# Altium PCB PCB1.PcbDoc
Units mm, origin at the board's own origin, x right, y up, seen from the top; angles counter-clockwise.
Board outline 70 x 70 mm, 2 copper layers (Top Layer, Bottom Layer); 5 components, 87 nets, 200 pads, 0 vias.
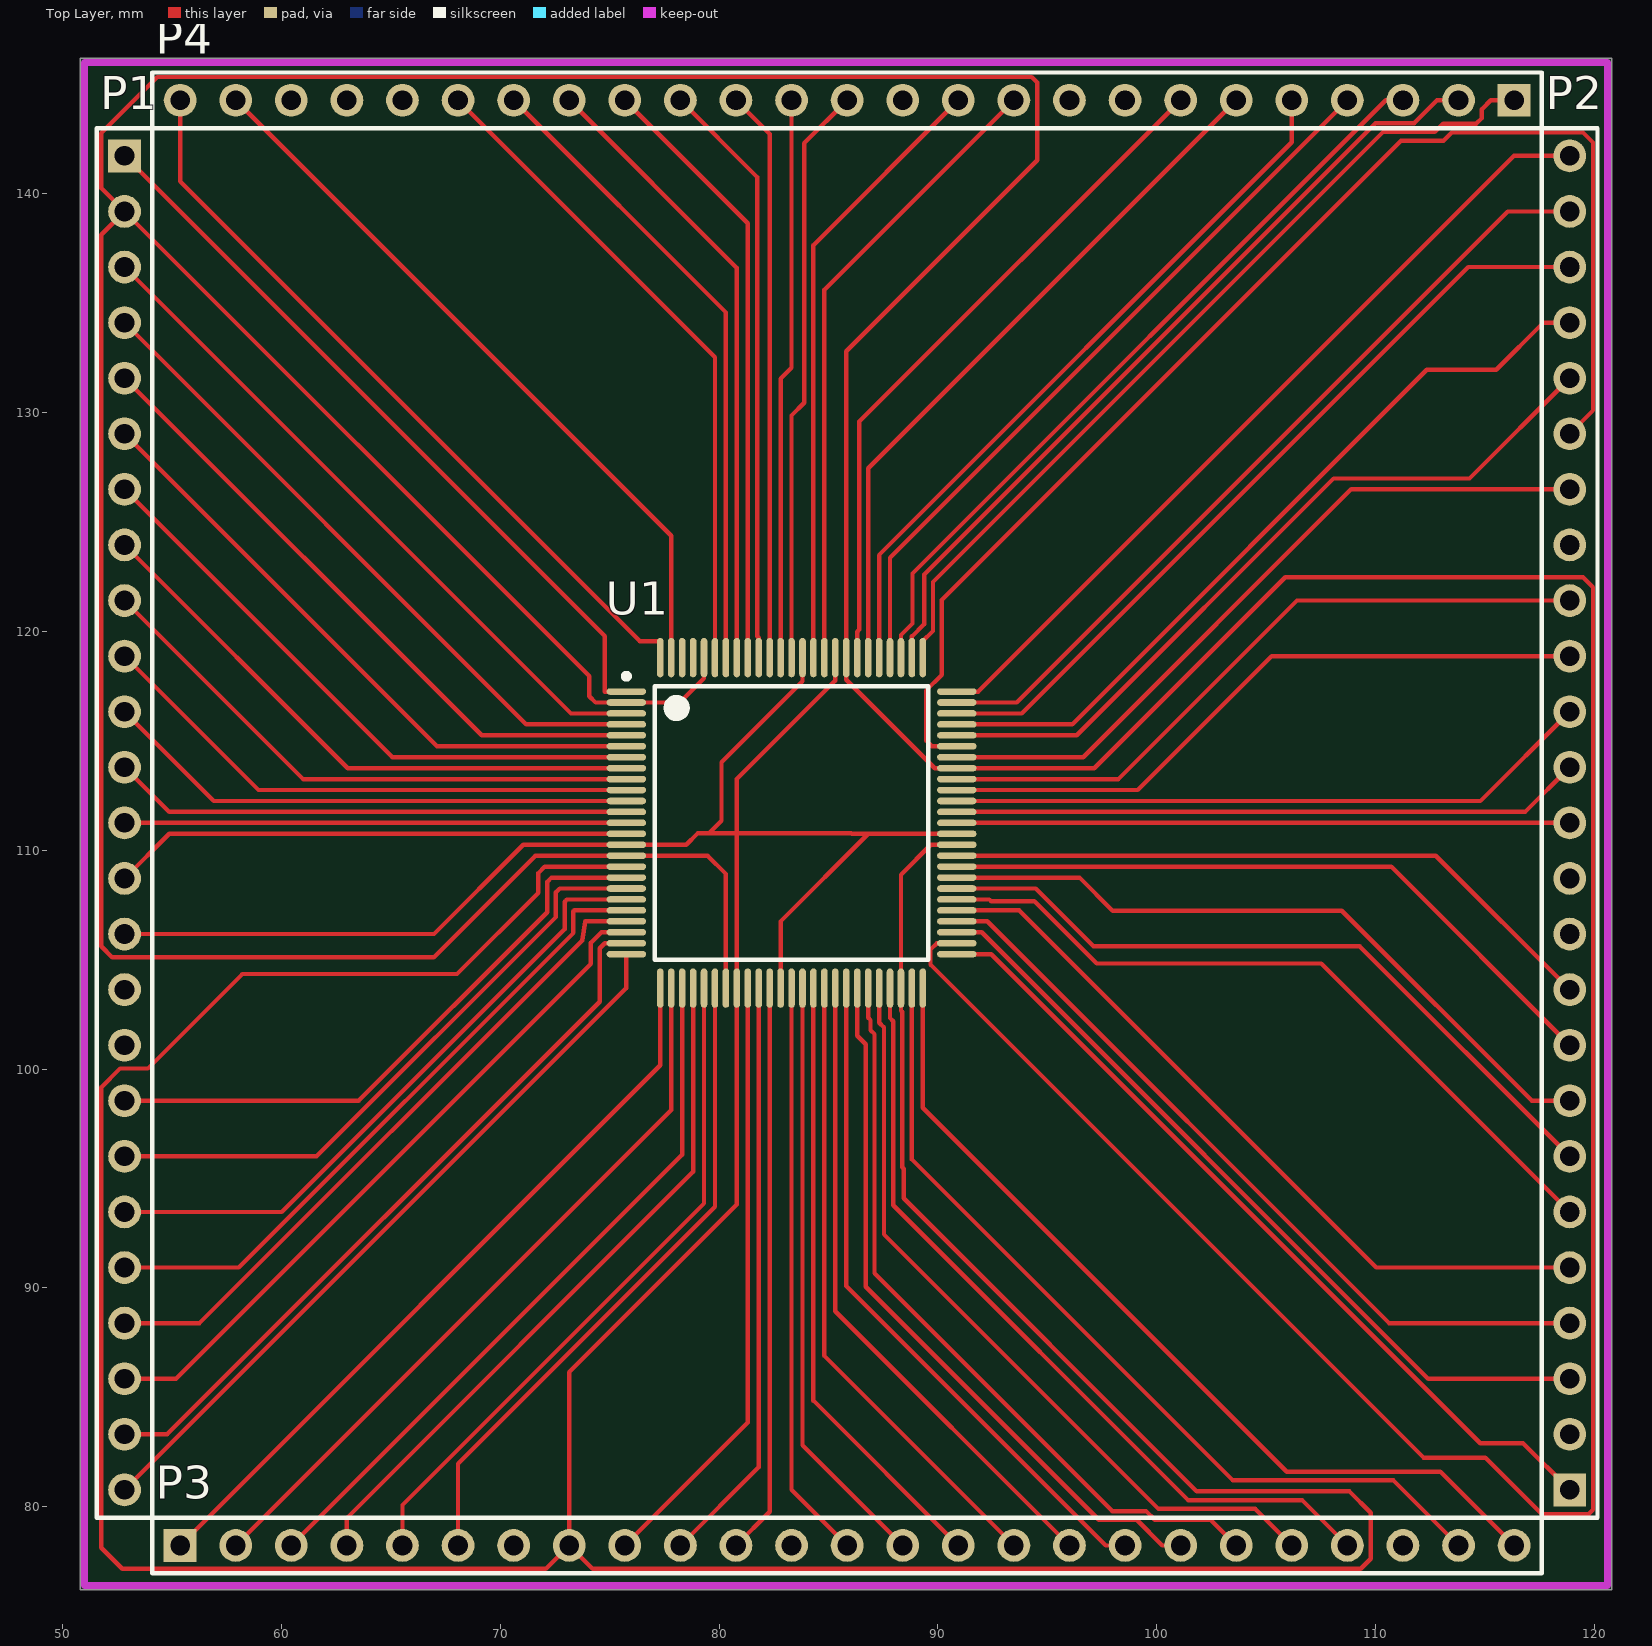
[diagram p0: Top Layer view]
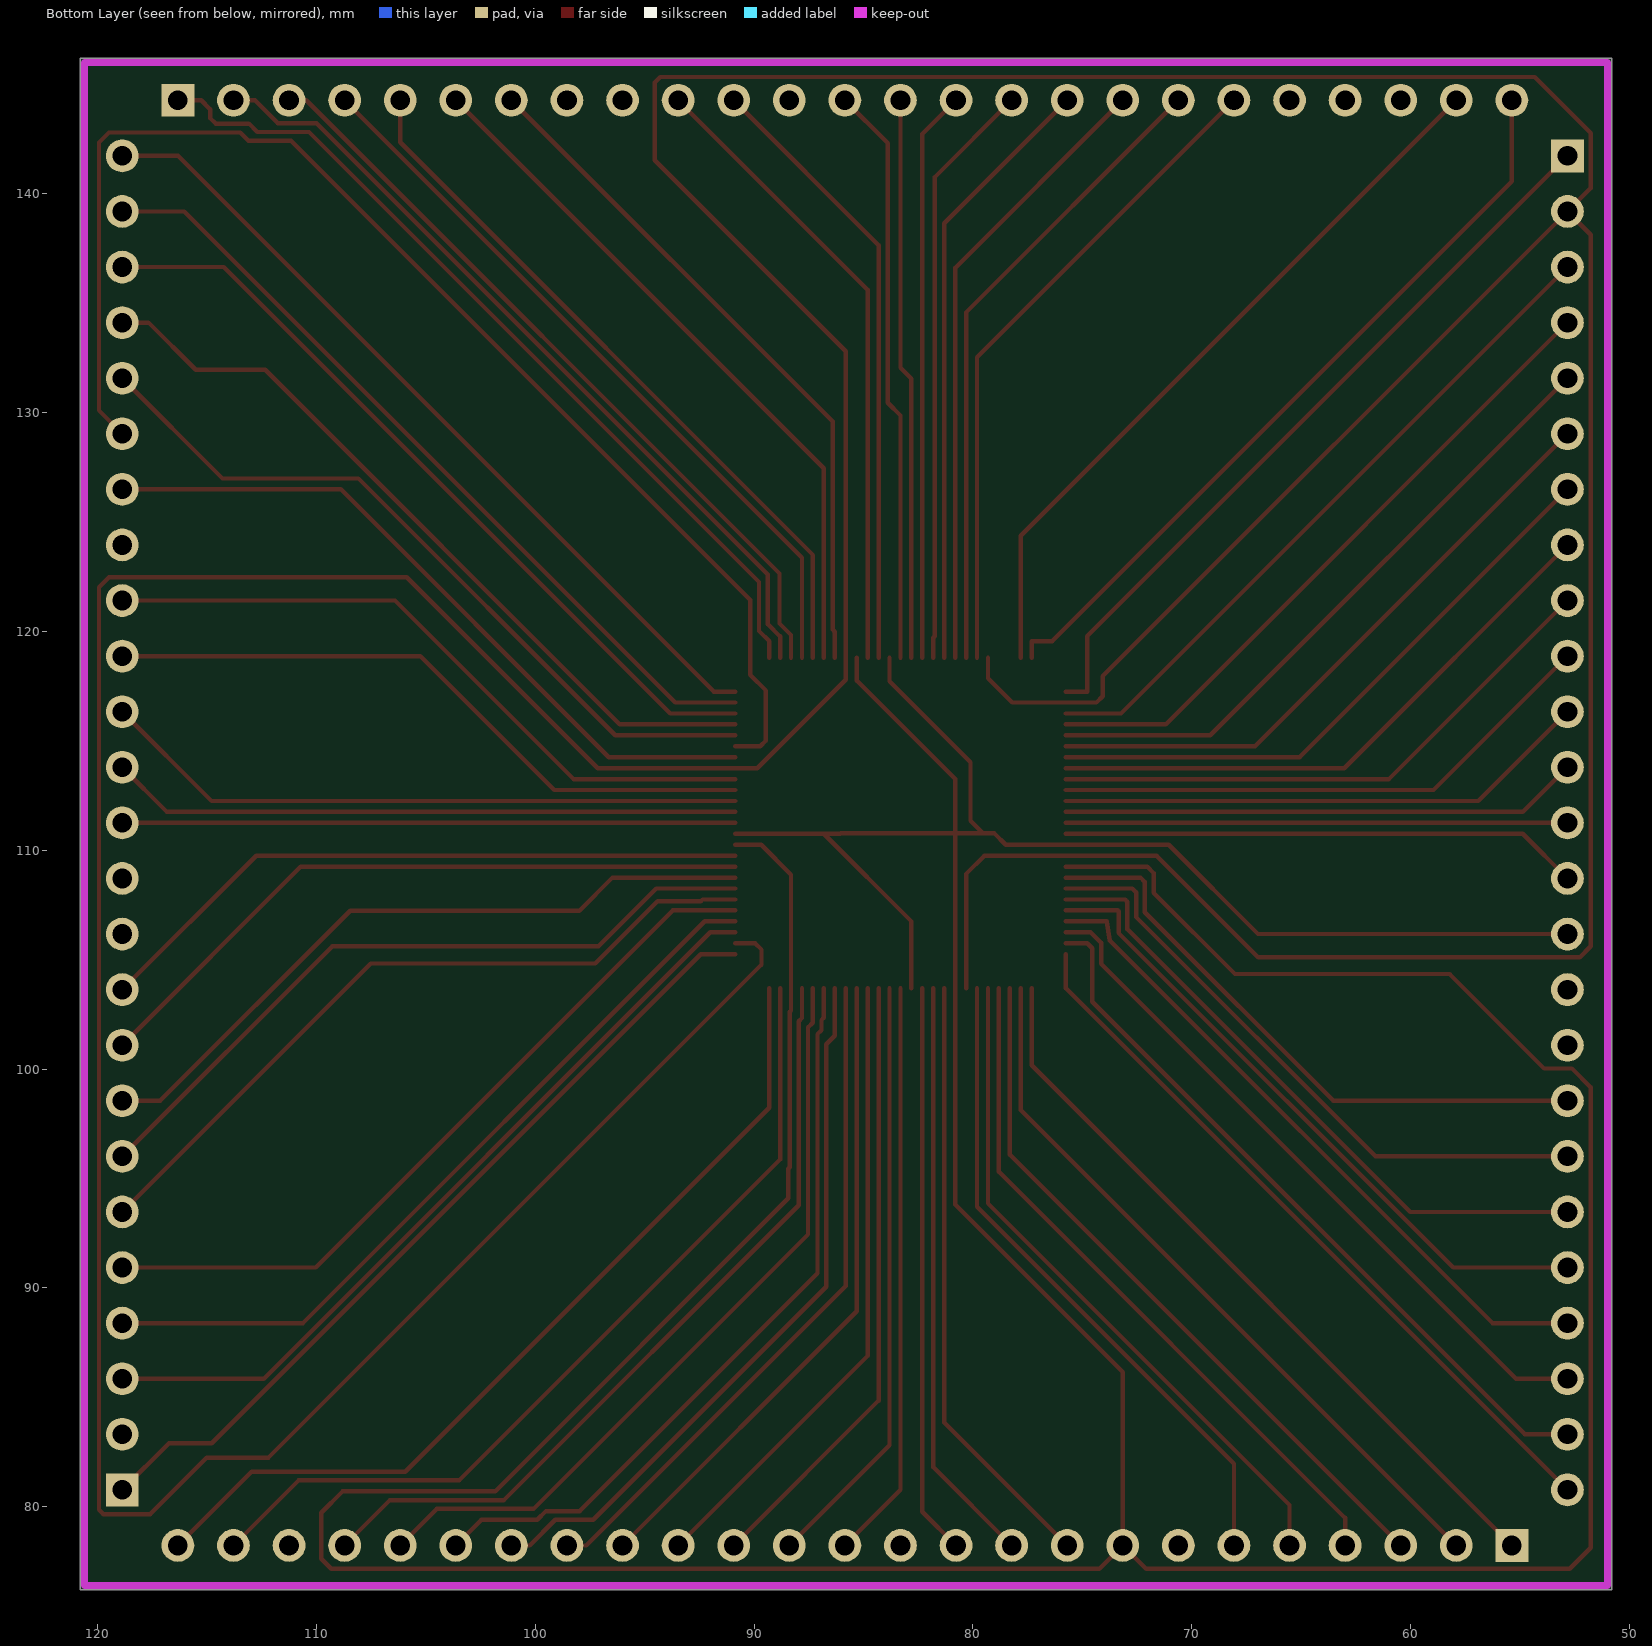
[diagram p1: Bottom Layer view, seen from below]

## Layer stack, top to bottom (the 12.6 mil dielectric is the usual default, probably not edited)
Top Layer: signal copper 0.0356
Dielectric: dielectric 0.32, FR-4, Dk 4.8
Bottom Layer: signal copper 0.0356

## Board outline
50.8,76.2 120.8,76.2 120.8,146.2 50.8,146.2

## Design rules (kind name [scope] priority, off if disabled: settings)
Clearance [All] p1: gap=0.2
ComponentClearance [All] p1: gap=0.254 collisioncheckmode=3 verticalgap=0.254
PolygonConnect [All] p1: connectstyle=Relief reliefconductorwidth=0.254 reliefentries=4 polygonreliefangle="90 Angle"
RoomDefinition CHIP [InComponentClass('CHIP')] p1: confinementstyle=ConfineIn formatcopy=TRUE lockcomponents=FALSE outline 0,0 50.8,0 50.8,25.4 0,25.4
RoutingLayers [All] p1: top layer_v5=TRUE bottom layer_v5=FALSE
RoutingVias [All] p1: holewidth=0.2 width=2 viastyle="Through Hole" minholewidth=0.711 minwidth=1.27 maxholewidth=0.711 maxwidth=1.27
SolderMaskExpansion [All] p1: expansion=0.102
TestPointUsage [All] p1: valid=0 allowmultiple=FALSE
Testpoint [All] p1: side=15 testpointundercomponent=TRUE minsize=1.016 maxsize=2.54 preferedsize=1.524 minholesize=0 maxholesize=1.016 preferedholesize=0.813 testpointgrid=0.025 style=1023 order=0123456789
Width [All] p1: maxlimit=0.2 minlimit=0.2 preferedwidth=0.2
17 further rules are at their usual default settings.

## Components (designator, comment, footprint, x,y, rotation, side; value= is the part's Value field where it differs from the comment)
P1 "1-25" HDR1X25 52.832,141.732 r270 top
P2 "51-75" HDR1X25 118.872,80.772 r90 top
P3 "26-50" HDR1X25 55.372,78.232 r0 top
P4 "76-100" HDR1X25 116.332,144.272 r180 top
U1 "AT91SAM7X256-AU" LQFP100_N 83.312,111.252 r0 top

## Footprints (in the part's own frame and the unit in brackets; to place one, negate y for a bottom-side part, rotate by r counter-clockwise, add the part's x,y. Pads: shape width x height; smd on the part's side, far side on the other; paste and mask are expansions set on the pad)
HDR1X25 [mm] "Connector; Header; 25 Position"
  rect 1.5x1.5 hole 0.9: 1(0,0)
  round 1.5 hole 0.9: 2(2.54,0) 3(5.08,0) 4(7.62,0) 5(10.16,0) 6(12.7,0) 7(15.24,0) 8(17.78,0) 9(20.32,0) 10(22.86,0) 11(25.4,0) 12(27.94,0) 13(30.48,0) 14(33.02,0) 15(35.56,0) 16(38.1,0) 17(40.64,0) 18(43.18,0) 19(45.72,0) 20(48.26,0) 21(50.8,0) 22(53.34,0) 23(55.88,0) 24(58.42,0) 25(60.96,0)
  silkscreen extent -1.27,-1.27 62.23,1.27
LQFP100_N [mm] "Thin QFP, 100-Leads, Body 14x14mm, Pitch 0.5mm, IPC Medium Density"
  oval 1.8x0.3 smd: 1(-7.55,6) 2(-7.55,5.5) 3(-7.55,5) 4(-7.55,4.5) 5(-7.55,4) 6(-7.55,3.5) 7(-7.55,3) 8(-7.55,2.5) 9(-7.55,2) 10(-7.55,1.5) 11(-7.55,1) 12(-7.55,0.5) 13(-7.55,0) 14(-7.55,-0.5) 15(-7.55,-1) 16(-7.55,-1.5) 17(-7.55,-2) 18(-7.55,-2.5) 19(-7.55,-3) 20(-7.55,-3.5) 21(-7.55,-4) 22(-7.55,-4.5) 23(-7.55,-5) 24(-7.55,-5.5) 25(-7.55,-6) 51(7.55,-6) 52(7.55,-5.5) 53(7.55,-5) 54(7.55,-4.5) 55(7.55,-4) 56(7.55,-3.5) 57(7.55,-3) 58(7.55,-2.5) 59(7.55,-2) 60(7.55,-1.5) 61(7.55,-1) 62(7.55,-0.5) 63(7.55,0) 64(7.55,0.5) 65(7.55,1) 66(7.55,1.5) 67(7.55,2) 68(7.55,2.5) 69(7.55,3) 70(7.55,3.5) 71(7.55,4) 72(7.55,4.5) 73(7.55,5) 74(7.55,5.5) 75(7.55,6)
  oval 0.3x1.8 smd: 26(-6,-7.55) 27(-5.5,-7.55) 28(-5,-7.55) 29(-4.5,-7.55) 30(-4,-7.55) 31(-3.5,-7.55) 32(-3,-7.55) 33(-2.5,-7.55) 34(-2,-7.55) 35(-1.5,-7.55) 36(-1,-7.55) 37(-0.5,-7.55) 38(0,-7.55) 39(0.5,-7.55) 40(1,-7.55) 41(1.5,-7.55) 42(2,-7.55) 43(2.5,-7.55) 44(3,-7.55) 45(3.5,-7.55) 46(4,-7.55) 47(4.5,-7.55) 48(5,-7.55) 49(5.5,-7.55) 50(6,-7.55) 76(6,7.55) 77(5.5,7.55) 78(5,7.55) 79(4.5,7.55) 80(4,7.55) 81(3.5,7.55) 82(3,7.55) 83(2.5,7.55) 84(2,7.55) 85(1.5,7.55) 86(1,7.55) 87(0.5,7.55) 88(0,7.55) 89(-0.5,7.55) 90(-1,7.55) 91(-1.5,7.55) 92(-2,7.55) 93(-2.5,7.55) 94(-3,7.55) 95(-3.5,7.55) 96(-4,7.55) 97(-4.5,7.55) 98(-5,7.55) 99(-5.5,7.55) 100(-6,7.55)
  silkscreen extent -7.67,-6.25 6.25,6.82, body extent -7,-7 7,7, height 1.6

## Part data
P1 P2 P3 P4: library part "Header 25", "Header, 25-Pin"
U1: "Smart ARM Microcontroller, ARM7TDMI 32-Bit RISC CPU, 256KB Flash and 64KB SRAM, 100-Pin LQFP, Industrial, Pb-Free"

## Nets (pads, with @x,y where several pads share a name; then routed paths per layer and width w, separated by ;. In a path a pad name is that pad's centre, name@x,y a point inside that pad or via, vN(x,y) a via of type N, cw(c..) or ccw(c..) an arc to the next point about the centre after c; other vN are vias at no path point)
AD4: P1.3 U1.3 | length 31.4
  Top Layer w0.2: P1.3 73.232,116.252 U1.3
AD5: P1.4 U1.4 | length 30.5
  Top Layer w0.2: P1.4 71.192,115.752 U1.4
AD6: P1.5 U1.5 | length 29.7
  Top Layer w0.2: P1.5 69.152,115.252 U1.5
AD7: P1.6 U1.6 | length 28.8
  Top Layer w0.2: P1.6 67.112,114.752 U1.6
ADVREF: P1.1 U1.1 | length 34.6
  Top Layer w0.2: P1.1 74.778,119.786 74.778,117.252 U1.1
DDM: P4.18 U1.93 | length 28.6
  Top Layer w0.2: P4.18 80.812,136.612 U1.93
DDP: P4.19 U1.94 | length 29.5
  Top Layer w0.2: P4.19 80.312,134.572 U1.94
ERASE: P4.17 U1.92 | length 27.8
  Top Layer w0.2: P4.17 81.312,138.652 U1.92
GND: P1.2 U1.2 U1.16 U1.32 U1.52 U1.68 U1.83 U1.96 | length 311.4
  Top Layer w0.2: U1.96 79.312,117.856 78.208,116.752 U1.2 74.358,116.752 74.066,117.043 74.066,117.958 P1.2 ; U1.32 80.312,108.915 79.475,109.752 U1.16 71.605,109.752 66.958,105.105 52.273,105.105 51.765,105.613 51.765,138.125 P1.2 ; U1.52 89.953,105.752 89.662,105.461 89.662,104.775 112.192,82.245 115.011,82.245 117.602,79.654 119.736,79.654 119.939,79.858 119.939,122.022 119.482,122.479 105.867,122.479 97.14,113.752 U1.68 89.854,113.752 85.812,117.794 U1.83 85.812,132.802 94.539,141.529 94.539,145.085 94.285,145.339 54.331,145.339 51.765,142.773 51.765,140.259 P1.2
JTAGSEL: P4.2 U1.77 | length 37.4
  Top Layer w0.2: U1.77 88.812,119.772 89.376,120.335 89.376,122.599 109.999,143.222 111.76,143.222 112.81,144.272 P4.2
NRST: P2.7 U1.57 | length 33.1
  Top Layer w0.2: U1.57 94.473,108.252 97.112,105.613 109.271,105.613 P2.7
PA0/PGMEN0/RXD0: P4.6 U1.81 | length 32.4
  Top Layer w0.2: U1.81 86.812,127.452 P4.6
PA1/PGMEN1/TXD0: P4.7 U1.82 | length 31.6
  Top Layer w0.2: U1.82 86.312,119.99 86.411,120.088 86.411,129.591 P4.7
"PA2 3/PGMD11/TD": P2.5 U1.55 | length 34.8
  Top Layer w0.2: U1.55 93.713,107.252 110.033,90.932 P2.5
"PA2 7/PGMD15/DRXD": P2.23 U1.73 | length 36.5
  Top Layer w0.2: U1.73 93.837,116.252 114.237,136.652 P2.23
PA2/SCK0: P4.11 U1.86 | length 28.2
  Top Layer w0.2: U1.86 84.312,137.652 P4.11
PA3/RTS0: P4.10 U1.85 | length 29.1
  Top Layer w0.2: U1.85 84.812,135.612 P4.10
PA4/PGMNCMD/CTS0: P4.13 U1.88 | length 26.5
  Top Layer w0.2: U1.88 83.312,129.87 83.896,130.454 83.896,142.316 P4.13
"PA5/PGMRDY/RX D 1": P4.14 U1.89 | length 25.7
  Top Layer w0.2: U1.89 82.812,131.547 83.312,132.047 P4.14
"PA6/PGMNOE/T X D1": P4.15 U1.90 | length 26.1
  Top Layer w0.2: P4.15 82.312,142.732 U1.90
PA7/PGMNVALID/SCK1: P4.16 U1.91 | length 27
  Top Layer w0.2: P4.16 81.737,140.767 81.737,119.785 81.812,119.71 U1.91
PA8/PGMM0/RTS1: P1.13 U1.13 | length 22.9
  Top Layer w0.2: P1.13 U1.13
PA9/PGMM1/CTS1: P1.14 U1.14 | length 23.8
  Top Layer w0.2: P1.14 54.872,110.752 U1.14
"PA10/PGMM2/TW D": P1.18 U1.18 | length 28
  Top Layer w0.2: P1.18 63.525,98.552 72.143,107.17 72.143,108.555 72.34,108.752 U1.18
"PA11/PGMM3/TW CK": P1.19 U1.19 | length 28.7
  Top Layer w0.2: P1.19 61.603,96.012 72.543,106.953 72.543,108.078 72.718,108.252 U1.19
PA12/PGMD0/SPI_NPCS0: P1.20 U1.20 | length 29.6
  Top Layer w0.2: P1.20 60.019,93.472 72.943,106.396 72.943,107.65 73.045,107.752 U1.20
PA13/PGMD1/SPI0_NPCS1: P1.21 U1.21 | length 30.3
  Top Layer w0.2: P1.21 58.051,90.932 73.343,106.224 73.343,107.208 73.388,107.252 U1.21
PA14/PGMD2/SPI0_NPCS2: P1.22 U1.22 | length 30.9
  Top Layer w0.2: P1.22 56.259,88.392 73.743,105.877 73.882,106.752 U1.22
PA15/PGMD3/SPI0_NPCS3: P1.23 U1.23 | length 31.9
  Top Layer w0.2: P1.23 55.183,85.852 74.143,104.812 74.143,105.77 74.625,106.252 U1.23
PA16/PGMD4/SPI0_MISO: P1.24 U1.24 | length 33.7
  Top Layer w0.2: P1.24 54.776,83.312 74.543,103.079 74.543,105.518 74.778,105.752 U1.24
PA17/PGMD5/SPI0_MOSI: P1.25 U1.25 | length 34
  Top Layer w0.2: P1.25 75.762,103.702 U1.25
PA18/PGMD6/SPI0_SPCK: P3.1 U1.26 | length 34.6
  Top Layer w0.2: P3.1 77.312,100.172 U1.26
PA19/PGMD7/CANRX: P3.21 U1.46 | length 35.9
  Top Layer w0.2: U1.46 87.312,102.616 87.322,102.606 87.322,102.122 87.539,101.905 87.539,92.446 100.082,79.903 104.501,79.903 P3.21
PA20/PGMD8/CANTX: P3.22 U1.47 | length 37.2
  Top Layer w0.2: U1.47 87.812,102.337 87.96,102.188 87.96,93.776 101.434,80.303 106.641,80.303 P3.22
PA21/PGMD9/TF: P3.24 U1.49 | length 40.1
  Top Layer w0.2: U1.49 88.812,95.871 103.481,81.203 110.821,81.203 P3.24
PA22/PGMD10/TK: P3.25 U1.50 | length 40.8
  Top Layer w0.2: U1.50 89.312,98.23 105.939,81.603 112.961,81.603 P3.25
PA24/PGMD12/RD: P2.6 U1.56 | length 33.9
  Top Layer w0.2: U1.56 92.354,107.752 92.433,107.673 94.409,107.673 97.257,104.826 107.518,104.826 P2.6
PA25/PGMD13/RK: P2.9 U1.59 | length 31.4
  Top Layer w0.2: U1.59 110.712,109.252 P2.9
PA26/PGMD14/RF: P2.10 U1.60 | length 30.5
  Top Layer w0.2: U1.60 112.752,109.752 P2.10
"PA28/DT X D": P2.24 U1.74 | length 37.3
  Top Layer w0.2: U1.74 93.598,116.752 116.038,139.192 P2.24
PA29/FIQ: P2.25 U1.75 | length 38.1
  Top Layer w0.2: U1.75 91.846,117.252 116.326,141.732 P2.25
PA30/IRQ0: P4.5 U1.80 | length 33.3
  Top Layer w0.2: U1.80 87.312,123.489 106.172,142.349 P4.5
PB0/ETXCK/EREFCK: P3.15 U1.40 | length 28.2
  Top Layer w0.2: U1.40 84.312,84.852 P3.15
PB1/ETXEN: P3.16 U1.41 | length 29.1
  Top Layer w0.2: U1.41 84.812,86.892 P3.16
PB2/ETX0: P3.17 U1.42 | length 29.9
  Top Layer w0.2: U1.42 85.312,88.932 P3.17
PB3/ETX1: P3.18 U1.43 | length 31.3
  Top Layer w0.2: U1.43 85.812,90.09 97.67,78.232 P3.18
PB4/ECRS: P2.4 U1.54 | length 35.6
  Top Layer w0.2: U1.54 92.253,106.752 110.613,88.392 P2.4
PB5/ERX0: P3.9 U1.34 | length 27.8
  Top Layer w0.2: P3.9 81.312,83.852 U1.34
PB6/ERX1: P3.6 U1.31 | length 30.3
  Top Layer w0.2: P3.6 68.072,81.966 79.812,93.706 U1.31
PB7/ERXER: P3.13 U1.38 | length 26.5
  Top Layer w0.2: U1.38 83.312,80.772 P3.13
PB8/EMDC: P3.3 U1.28 | length 32.9
  Top Layer w0.2: P3.3 78.312,96.092 U1.28
PB9/EMDIO: P3.2 U1.27 | length 33.7
  Top Layer w0.2: P3.2 77.812,98.132 U1.27
PB10/ETX2: P3.19 U1.44 | length 33.1
  Top Layer w0.2: U1.44 86.312,101.528 86.702,101.137 86.702,90.049 97.35,79.402 99.084,79.402 100.254,78.232 P3.19
PB11/ETX3: P3.20 U1.45 | length 34.8
  Top Layer w0.2: U1.45 86.812,102.349 86.922,102.239 86.922,101.778 87.102,101.598 87.102,90.665 97.966,79.802 99.509,79.802 99.908,79.403 102.461,79.403 P3.20
PB12/ETXER: P3.14 U1.39 | length 27.4
  Top Layer w0.2: U1.39 83.812,82.812 P3.14
PB13/ERX2: P3.5 U1.30 | length 31.2
  Top Layer w0.2: P3.5 65.532,80.081 79.312,93.861 U1.30
PB14/ERX3: P3.4 U1.29 | length 32
  Top Layer w0.2: P3.4 62.992,79.49 78.812,95.31 U1.29
PB15/ERXDV/ECRSDV: P3.10 U1.35 | length 27
  Top Layer w0.2: P3.10 81.812,81.812 U1.35
PB16/ECOL: P2.3 U1.53 | length 36.5
  Top Layer w0.2: U1.53 91.999,106.252 112.399,85.852 P2.3
PB17/ERXCK: P3.11 U1.36 | length 26.1
  Top Layer w0.2: P3.11 82.312,79.772 U1.36
PB18/EF100: P2.13 U1.63 | length 28
  Top Layer w0.2: U1.63 P2.13
PB19/PWM0: P2.14 U1.64 | length 28.9
  Top Layer w0.2: U1.64 116.832,111.752 P2.14
PB20/PWM1: P2.15 U1.65 | length 29.7
  Top Layer w0.2: U1.65 114.792,112.252 P2.15
PB21/PWM2: P2.16 U1.66 | length 30.5
  Top Layer w0.2: U1.66 99.134,112.752 105.254,118.872 P2.16
PB22/PWM3: P2.17 U1.67 | length 31.4
  Top Layer w0.2: U1.67 98.248,113.252 106.408,121.412 P2.17
PB23/TIOA0: P2.19 U1.69 | length 33.1
  Top Layer w0.2: U1.69 96.64,114.252 108.881,126.492 P2.19
PB24/TIOB0: P2.20 U1.70 | length 60.8
  Top Layer w0.2: U1.70 89.718,114.752 89.459,115.011 89.459,117.297 90.176,118.014 90.176,121.435 111.163,142.422 113.102,142.422 113.479,142.799 119.482,142.799 119.939,142.342 119.939,130.099 P2.20
PB25/TIOA1: P2.21 U1.71 | length 34.8
  Top Layer w0.2: U1.71 96.343,115.252 108.081,126.99 114.29,126.99 P2.21
PB26/TIOB1: P2.22 U1.72 | length 35.6
  Top Layer w0.2: U1.72 96.143,115.752 112.344,131.953 115.519,131.953 117.678,134.112 P2.22
PB27/AD0/TIOA2: P1.9 U1.9 | length 26.3
  Top Layer w0.2: P1.9 60.992,113.252 U1.9
PB28/AD1/TIOB2: P1.10 U1.10 | length 25.5
  Top Layer w0.2: P1.10 58.952,112.752 U1.10
PB29/AD2/PCK1: P1.11 U1.11 | length 24.6
  Top Layer w0.2: P1.11 56.912,112.252 U1.11
PB30/AD3/PCK2: P1.12 U1.12 | length 23.8
  Top Layer w0.2: P1.12 54.872,111.752 U1.12
PLLRC: P4.24 U1.99 | length 33.7
  Top Layer w0.2: P4.24 77.812,124.372 U1.99
TCK: P4.4 U1.79 | length 34.1
  Top Layer w0.2: U1.79 87.812,123.372 P4.4
TDI: P2.1 U1.51 | length 38.1
  Top Layer w0.2: U1.51 92.433,105.252 114.78,82.906 116.738,82.906 P2.1
TDO: P4.1 U1.76 | length 39.6
  Top Layer w0.2: U1.76 89.312,119.558 89.776,120.021 89.776,122.258 110.34,142.822 112.702,142.822 113.085,143.205 114.605,143.205 114.859,143.459 114.859,143.866 115.265,144.272 P4.1
TMS: P4.3 U1.78 | length 35.4
  Top Layer w0.2: U1.78 88.312,119.837 88.838,120.363 88.838,122.645 110.465,144.272 P4.3
TST: P2.8 U1.58 | length 32.2
  Top Layer w0.2: U1.58 96.47,108.752 97.983,107.239 108.458,107.239 117.145,98.552 P2.8
VDDCORE: P1.15 U1.15 U1.37 U1.62 U1.87 | length 58.5
  Top Layer w0.2: P1.15 66.971,106.172 71.051,110.252 U1.15 78.502,110.252 79.019,110.769 79.527,110.769 ; U1.37 82.812,106.747 86.817,110.752 ; U1.87 83.812,117.721 80.112,114.021 80.112,111.354 79.527,110.769 ; U1.62 86.817,110.752 ; 79.527,110.769 86.038,110.769 86.055,110.752 86.817,110.752
VDDFLASH: P4.20 U1.95 | length 30.3
  Top Layer w0.2: P4.20 79.812,132.532 U1.95
VDDIN: P1.8 U1.8 | length 27.2
  Top Layer w0.2: P1.8 63.032,113.752 U1.8
VDDIO: P3.8 U1.17 U1.33 U1.48 U1.61 U1.84 | length 202.2
  Top Layer w0.2: U1.17 72.033,109.252 71.743,108.962 71.743,108.062 68.024,104.343 58.217,104.343 53.899,100.025 52.629,100.025 51.765,99.162 51.765,78.13 52.73,77.165 72.085,77.165 P3.8 ; U1.84 85.312,117.754 80.812,113.254 U1.33 80.812,93.812 73.152,86.152 P3.8 ; U1.61 89.678,110.252 88.312,108.886 U1.48 88.312,102.671 88.367,102.616 88.367,95.517 88.436,95.447 88.436,94.095 101.829,80.703 108.807,80.703 109.779,79.731 109.779,77.622 109.322,77.165 74.219,77.165 P3.8
VDDOUT: P1.7 U1.7 | length 28
  Top Layer w0.2: P1.7 65.072,114.252 U1.7
VDDPLL: P4.25 U1.100 | length 35.1
  Top Layer w0.2: P4.25 55.372,140.564 76.378,119.558 77.312,119.558 U1.100
XIN/PGMCK: P4.22
XOUT: P4.23
pads on no net: P1.16 P1.17 P2.2 P2.11 P2.12 P2.18 P3.7 P3.12 P3.23 P4.8 P4.9 P4.12 P4.21 U1.97 U1.98

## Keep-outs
Keep-Out Layer:
  lines w0.3: 51,76.4 51,146 120.6,146 120.6,76.4 51,76.4

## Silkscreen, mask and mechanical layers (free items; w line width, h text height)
Drill Drawing:
  text ".LEGEND" at 125.88,81.28 h1.52
  text "Drill Drawing." at 125.88,78.74 h1.52

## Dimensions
51,76.4 to 51,146 on Mechanical 1
51,76.4 to 120.6,76.4 on Mechanical 1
